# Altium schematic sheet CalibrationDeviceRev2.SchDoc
size A2; SheetNumber: 1; SheetTotal: 1; SPICEModelCacheJMJTSHEM: <root> / <DocumentId>JMJTSHEM</DocumentId> / </root>
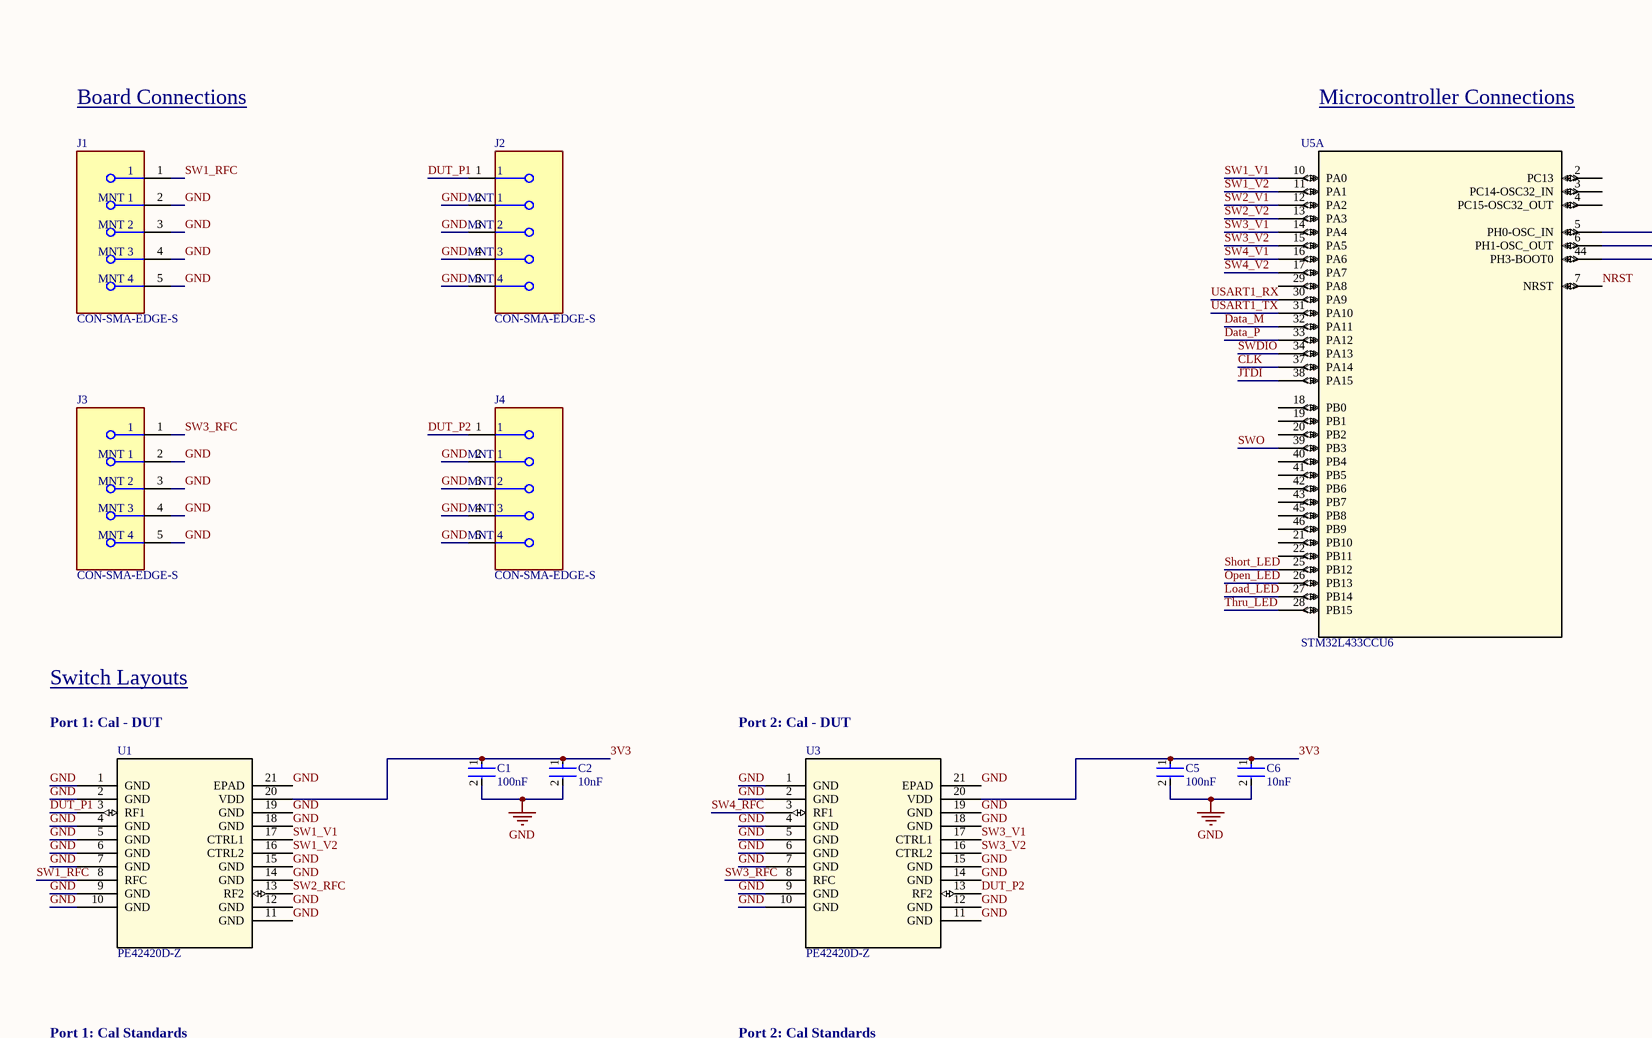
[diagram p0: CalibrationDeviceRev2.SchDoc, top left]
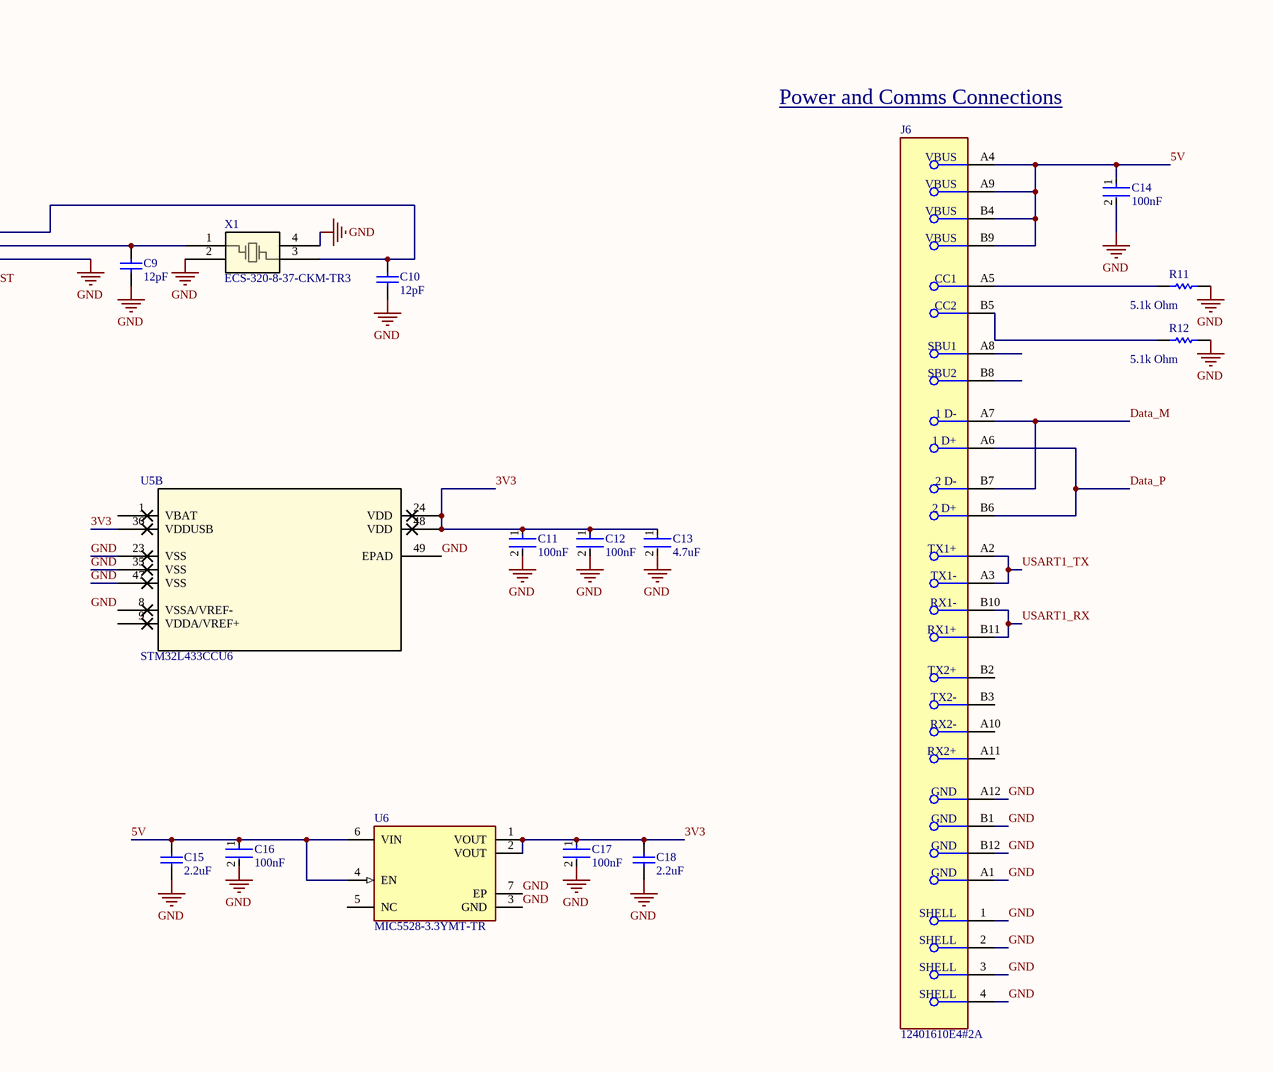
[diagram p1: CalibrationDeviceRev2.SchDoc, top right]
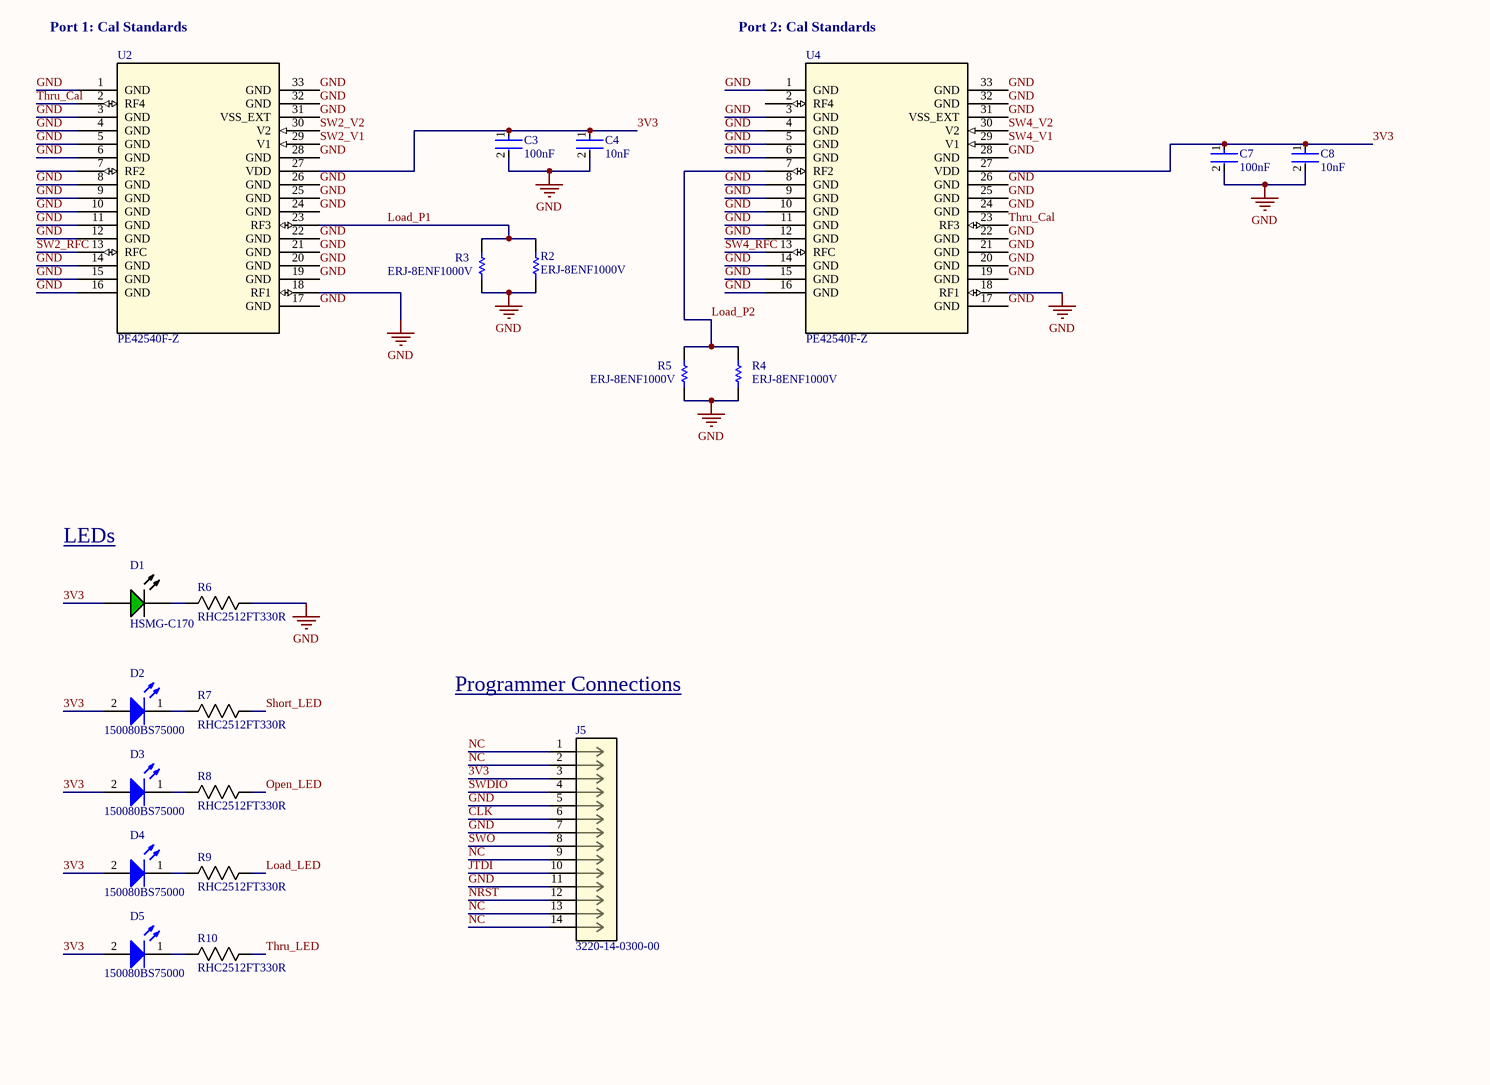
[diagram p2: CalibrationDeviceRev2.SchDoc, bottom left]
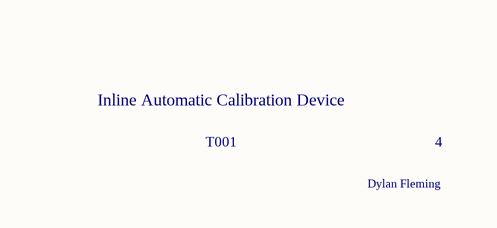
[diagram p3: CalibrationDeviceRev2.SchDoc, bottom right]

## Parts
C1  100nF  [FP-1206-L_3_2_0_2-W_1_6_0-MFG]
C2  10nF  [FP-C0805C-DN-MFG]
C3  100nF  [FP-1206-L_3_2_0_2-W_1_6_0-MFG]
C4  10nF  [FP-C0805C-DN-MFG]
C5  100nF  [FP-1206-L_3_2_0_2-W_1_6_0-MFG]
C6  10nF  [FP-C0805C-DN-MFG]
C7  100nF  [FP-1206-L_3_2_0_2-W_1_6_0-MFG]
C8  10nF  [FP-C0805C-DN-MFG]
C9  12pF  [CAPC2013X115X51NL20T26]
C10  12pF  [CAPC2013X115X51NL20T26]
C11  100nF  [FP-1206-L_3_2_0_2-W_1_6_0-MFG]
C12  100nF  [FP-1206-L_3_2_0_2-W_1_6_0-MFG]
C13  4.7uF  [FP-C2012-125-0_2-IPC_C]
C14  100nF  [FP-1206-L_3_2_0_2-W_1_6_0-MFG]
C15  2.2uF  [CAPC2013X145X50ML20T25]
C16  100nF  [FP-1206-L_3_2_0_2-W_1_6_0-MFG]
C17  100nF  [FP-1206-L_3_2_0_2-W_1_6_0-MFG]
C18  2.2uF  [CAPC2013X145X50ML20T25]
D1  HSMG-C170  [AVAG-HSMX-C170_V]
D2  150080BS75000  [WL-SMCW_0805_150080xx75000]
D3  150080BS75000  [WL-SMCW_0805_150080xx75000]
D4  150080BS75000  [WL-SMCW_0805_150080xx75000]
D5  150080BS75000  [WL-SMCW_0805_150080xx75000]
J1  CON-SMA-EDGE-S  [FP-CON-SMA-EDGE-S-MFG]
J2  CON-SMA-EDGE-S  [FP-CON-SMA-EDGE-S-MFG]
J3  CON-SMA-EDGE-S  [FP-CON-SMA-EDGE-S-MFG]
J4  CON-SMA-EDGE-S  [FP-CON-SMA-EDGE-S-MFG]
J5  3220-14-0300-00  [CONN_3220-14-0300-00_CNC]
J6  12401610E4#2A  [FP-12401610E4#2A-MFG]
R2  ERJ-8ENF1000V  [RESC3216X70X50NL05T20]
R3  ERJ-8ENF1000V  [RESC3216X70X50NL05T20]
R4  ERJ-8ENF1000V  [RESC3216X70X50NL05T20]
R5  ERJ-8ENF1000V  [RESC3216X70X50NL05T20]
R6  RHC2512FT330R  [STA_RHC2512_STP]
R7  RHC2512FT330R  [STA_RHC2512_STP]
R8  RHC2512FT330R  [STA_RHC2512_STP]
R9  RHC2512FT330R  [STA_RHC2512_STP]
R10  RHC2512FT330R  [STA_RHC2512_STP]
R11  5.1k Ohm  [RESC3216X50X50NL20T25]
R12  5.1k Ohm  [RESC3216X50X50NL20T25]
U1  PE42420D-Z  [LGA20_4X4_PSM]
U2  PE42540F-Z  [PE42540G-Z]
U3  PE42420D-Z  [LGA20_4X4_PSM]
U4  PE42540F-Z  [PE42540G-Z]
U5  STM32L433CCU6  [UFQFPN48-7x7mm]  (parts A,B of 2)
U6  MIC5528-3.3YMT-TR  [FP-TDFN1212-6LD-PL-1-MFG]
X1  ECS-320-8-37-CKM-TR3  [NX2016SA_NDK]

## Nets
GND: C1.2 C2.2 C3.2 C4.2 C5.2 C6.2 C7.2 C8.2 C9.1 C10.1 C11.2 C12.2 C13.2 C14.2 C15.1 C16.2 C17.2 C18.1 J1.2(MNT_1) J1.3(MNT_2) J1.4(MNT_3) J1.5(MNT_4) J2.2(MNT_1) J2.3(MNT_2) J2.4(MNT_3) J2.5(MNT_4) J3.2(MNT_1) J3.3(MNT_2) J3.4(MNT_3) J3.5(MNT_4) J4.2(MNT_1) J4.3(MNT_2) J4.4(MNT_3) J4.5(MNT_4) J5.5 J5.7 J5.11 J6.1(SHELL) J6.2(SHELL) J6.3(SHELL) J6.4(SHELL) J6.A1(GND) J6.A12(GND) J6.B1(GND) J6.B12(GND) R2.2 R3.2 R4.2 R5.2 R6.2 R11.2 R12.2 U1.1(GND) U1.2(GND) U1.4(GND) U1.5(GND) U1.6(GND) U1.7(GND) U1.9(GND) U1.10(GND) U1.11(GND) U1.12(GND) U1.14(GND) U1.15(GND) U1.18(GND) U1.19(GND) U1.21(EPAD) U2.1(GND) U2.3(GND) U2.4(GND) U2.5(GND) U2.6(GND) U2.8(GND) U2.9(GND) U2.10(GND) U2.11(GND) U2.12(GND) U2.14(GND) U2.15(GND) U2.16(GND) U2.17(GND) U2.18(RF1) U2.19(GND) U2.20(GND) U2.21(GND) U2.22(GND) U2.24(GND) U2.25(GND) U2.26(GND) U2.28(GND) U2.31(VSS_EXT) U2.32(GND) U2.33(GND) U3.1(GND) U3.2(GND) U3.4(GND) U3.5(GND) U3.6(GND) U3.7(GND) U3.9(GND) U3.10(GND) U3.11(GND) U3.12(GND) U3.14(GND) U3.15(GND) U3.18(GND) U3.19(GND) U3.21(EPAD) U4.1(GND) U4.3(GND) U4.4(GND) U4.5(GND) U4.6(GND) U4.8(GND) U4.9(GND) U4.10(GND) U4.11(GND) U4.12(GND) U4.14(GND) U4.15(GND) U4.16(GND) U4.17(GND) U4.18(RF1) U4.19(GND) U4.20(GND) U4.21(GND) U4.22(GND) U4.24(GND) U4.25(GND) U4.26(GND) U4.28(GND) U4.31(VSS_EXT) U4.32(GND) U4.33(GND) U5.23(VSS) U5.35(VSS) U5.44(PH3-BOOT0) U5.47(VSS) U5.49(EPAD) U6.3(GND) U6.7(EP) X1.2 X1.4
3V3: C1.1 C2.1 C3.1 C4.1 C5.1 C6.1 C7.1 C8.1 C11.1 C12.1 C13.1 C17.1 C18.2 D1.1(A) D2.2(A) D3.2(A) D4.2(A) D5.2(A) J5.3 U1.20(VDD) U2.27(VDD) U3.20(VDD) U4.27(VDD) U5.24(VDD) U5.36(VDDUSB) U5.48(VDD) U6.1(VOUT) U6.2(VOUT)
5V: C14.1 C15.2 C16.1 J6.A4(VBUS) J6.A9(VBUS) J6.B4(VBUS) J6.B9(VBUS) U6.4(EN) U6.6(VIN)
CLK: J5.6 U5.37(PA14)
Data_M: J6.A7(1_D-) J6.B7(2_D-) U5.32(PA11)
Data_P: J6.A6(1_D+) J6.B6(2_D+) U5.33(PA12)
DUT_P1: J2.1 U1.3(RF1)
DUT_P2: J4.1 U3.13(RF2)
JTDI: J5.10 U5.38(PA15)
Load_LED: R9.2 U5.27(PB14)
Load_P1: R2.1 R3.1 U2.23(RF3)
Load_P2: R4.1 R5.1 U4.7(RF2)
NC: J5.1 J5.2 J5.9 J5.13 J5.14
NRST: J5.12 U5.7(NRST)
Open_LED: R8.2 U5.26(PB13)
Short_LED: R7.2 U5.25(PB12)
SW1_RFC: J1.1 U1.8(RFC)
SW1_V1: U1.17(CTRL1) U5.10(PA0)
SW1_V2: U1.16(CTRL2) U5.11(PA1)
SW2_RFC: U1.13(RF2) U2.13(RFC)
SW2_V1: U2.29(V1) U5.12(PA2)
SW2_V2: U2.30(V2) U5.13(PA3)
SW3_RFC: J3.1 U3.8(RFC)
SW3_V1: U3.17(CTRL1) U5.14(PA4)
SW3_V2: U3.16(CTRL2) U5.15(PA5)
SW4_RFC: U3.3(RF1) U4.13(RFC)
SW4_V1: U4.29(V1) U5.16(PA6)
SW4_V2: U4.30(V2) U5.17(PA7)
SWDIO: J5.4 U5.34(PA13)
SWO: J5.8 U5.39(PB3)
Thru_Cal: U2.2(RF4) U4.23(RF3)
Thru_LED: R10.2 U5.28(PB15)
USART1_RX: J6.B10(RX1-) J6.B11(RX1+) U5.30(PA9)
USART1_TX: J6.A2(TX1+) J6.A3(TX1-) U5.31(PA10)
NetC9_2: C9.2 U5.6(PH1-OSC_OUT) X1.1
NetC10_2: C10.2 U5.5(PH0-OSC_IN) X1.3
NetD1_2: D1.2(K) R6.1
NetD2_1: D2.1(K) R7.1
NetD3_1: D3.1(K) R8.1
NetD4_1: D4.1(K) R9.1
NetD5_1: D5.1(K) R10.1
NetJ6_A5: J6.A5(CC1) R11.1
NetJ6_B5: J6.B5(CC2) R12.1

Not connected (* = marked no-connect by the designer): J6 A8(SBU1) A10(RX2-) A11(RX2+) B2(TX2+) B3(TX2-) B8(SBU2); U2 7(RF2); U4 2(RF4); U5 1(VBAT) 2(PC13) 3(PC14-OSC32_IN) 4(PC15-OSC32_OUT) 8(VSSA/VREF-) 9(VDDA/VREF+) 18(PB0) 19(PB1) 20(PB2) 21(PB10) 22(PB11) 29(PA8) 40(PB4) 41(PB5) 42(PB6) 43(PB7) 45(PB8) 46(PB9); U6 5(NC)

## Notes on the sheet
- Board Connections
- Microcontroller Connections
- Power and Comms Connections
- Switch Layouts
- Port 1: Cal - DUT
- Port 2: Cal - DUT
- Port 1: Cal Standards
- Port 2: Cal Standards
- LEDs
- Programmer Connections
- Inline Automatic Calibration Device
- T001
- Dylan Fleming
- 4
- Labels drawn without touching a wire or pin: GND

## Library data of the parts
C1 C3 C5 C7 C11 C12 C14 C16 C17 = CMP-04427-004798-1: General Purpose Ceramic Capacitor, 1206, 100nF, 10%, X7R, 15%, 100V
C2 C4 C6 C8 = CMP-2007-00259-2: CAP CER 10000PF 200V X7R 0805; Manufacturer Part Number: C0805C103K2RACTU; Manufacturer: KEMET; Material: Ceramic; Temperature Coefficient: 30ppm/°C; Capacitance: 10,000 pF; Tolerance: 0.1; Value: 10,000 pF
C9 C10 = CMP-2007-04862-1: Manufacturer: AVX Interconnect / Elco; Part Number: 08052U120GAT2A
C13 = CMP-08246-000007-2: Multilayer Ceramic Capacitors 4.7μF ±10% 50V X5R SMD 0805
C15 C18 = CMP-1036-04819-2: Part Number: C0805C225K9PACTU; Manufacturer: Kemet
D1 = CMP-2000-05062-1: Chip LED, Green, 2.2 V, -40 to 85 degC, 2-Pin SMD, Pb-Free, Tape and Reel; Manufacturer: Avago; No. of Pins: 2; Peak Wavelength: 570nm; SVHC: NoSVHC(16-Jun-2014); Dominant Wavelength: 572nm; Forward Current If: 20mA; Viewing Angle: 170deg; Lens Shape: Rectangular; PIV Max: 5V; External Width: 1.25mm; LED Type: Standard; External Depth: 0.8mm; Opto Mounting Orientation: Top; Luminous Intensity: 15mcd; Luminous Intensity Min: 4mcd; Forward Voltage VF Max: 2.6V; External Length / Height: 2mm; Bulb Size: 1.25mmx1.4mm; Light Area Height: 1mm; Voltage Vf Typ: 2.2V
D2-D5 = CMP-1426-00008-6: NexarPartId: 29717779; Test Current: 20mA; Lens Style: Clear, Rectangular; Forward Current: 100mA; Power Dissipation: 105mW; Dominant Wavelength: 470nm; Reverse Voltage: 5V; Viewing Angle: 140°; Luminous Intensity: 145mcd; Color: Blue; Forward Voltage: 3.2V; Max Junction Temperature (Tj): 95°C; Peak Wavelength: 465nm
J1-J4 = CMP-204357-000001-1: CONN SMA JACK STR EDGE MNT; Manufacturer: RF Solutions Ltd.; Impedance: 50Ω; Conn Orientation: Right Angle; Is Female: yes; Number Of Contacts: 1; Frequency: 18GHz; Shielding: true
J5 = 3220-14-0300-00: No Description Available; Mfr_Name: CNC Tech
J6 = CMP-15126-126516878-1: 12401610E4#2A Conn USB Type C RCP 24 POS 0.5mm Solder RA SMD 24 Terminal 1 Port Automotive; Gender: Receptacle; USB Standard: USB 3.1; Number of Contacts: 24; Current Rating: 5A
R2-R5 = CMP-2003-00016-1: Manufacturer: Panasonic
R6-R10 = RHC2512FT330R: No Description Available; Mfr_Name: Stackpole International
R11 R12 = CMP-2003-02609-1: Part Number: RG3216P-5101-B-T5; Manufacturer: Susumu
U1 U3 = PE42420D-Z: No Description Available; Mfr_Name: pSemi
U2 U4 = PE42540F-Z: No Description Available; Mfr_Name: Peregine Semiconductor
U5 = STM32L433CCU6: No Description Available; Mfr_Name: STMicroelectronics
U6 = CMP-06324-000078-1: IC REG LINEAR 3.3V 500MA 6TDFN; Dropout Voltage: 260mV; Number of Regulators: 1; Min Current Limit: 525mA
X1 = NX2016SA-32M-EXS00A-CS06465: No Description Available; Mfr_Name: NDK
